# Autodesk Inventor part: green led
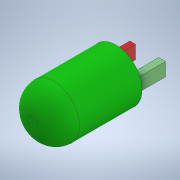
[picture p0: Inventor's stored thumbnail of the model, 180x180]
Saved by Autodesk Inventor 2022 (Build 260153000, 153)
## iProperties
Created: 2021-06
Part Number: green led
Material: Generic
Document SubType Name: Modeling
Designer: Dell
Density: 1 g/cm^3
Appearance: Default
Author: Dell
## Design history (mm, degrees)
sketch "Sketch1"
  geometry: C1 r 2.5 at (0, 0); 1 further point
  constraints: 1 centre point, 1 coincident
  dimensions: "d0" = 5 diameter of C1
extrude "Extrusion1" new body sketch "Sketch1" distance "d1" = 8; taper "d2" = 0 deg
fillet "Fillet1" dims "d3" = 2
sketch "Sketch2"
  geometry: L1 (1.668, 0.5)-(1.114, 0.5); L2 (1.114, 0.5)-(1.114, -0.783); L3 (1.114, -0.783)-(1.668, -0.783); L4 (1.668, -0.783)-(1.668, 0.5); L5 (-1.096, 0.5)-(-1.755, 0.5); L6 (-1.755, 0.5)-(-1.755, -0.783); L7 (-1.755, -0.783)-(-1.096, -0.783); L8 (-1.096, -0.783)-(-1.096, 0.5); 1 further point
  constraints: 16 end point, 4 parallel, 2 horizontal, 2 perpendicular, 2 point on line
extrude "Extrusion2" join sketch "Sketch2" distance "d4" = 3; taper "d5" = 0 deg
body "Solid1"
